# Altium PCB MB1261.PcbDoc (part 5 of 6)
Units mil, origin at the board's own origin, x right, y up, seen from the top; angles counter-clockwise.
Board outline 5119.1 x 2638.79 mil, 6 copper layers (TOP, L2_GND, L3_SIG, L4_VCC, L5_GND, BOTTOM), stack 61 mil thick; 336 components, 316 nets, 1358 pads, 871 vias.
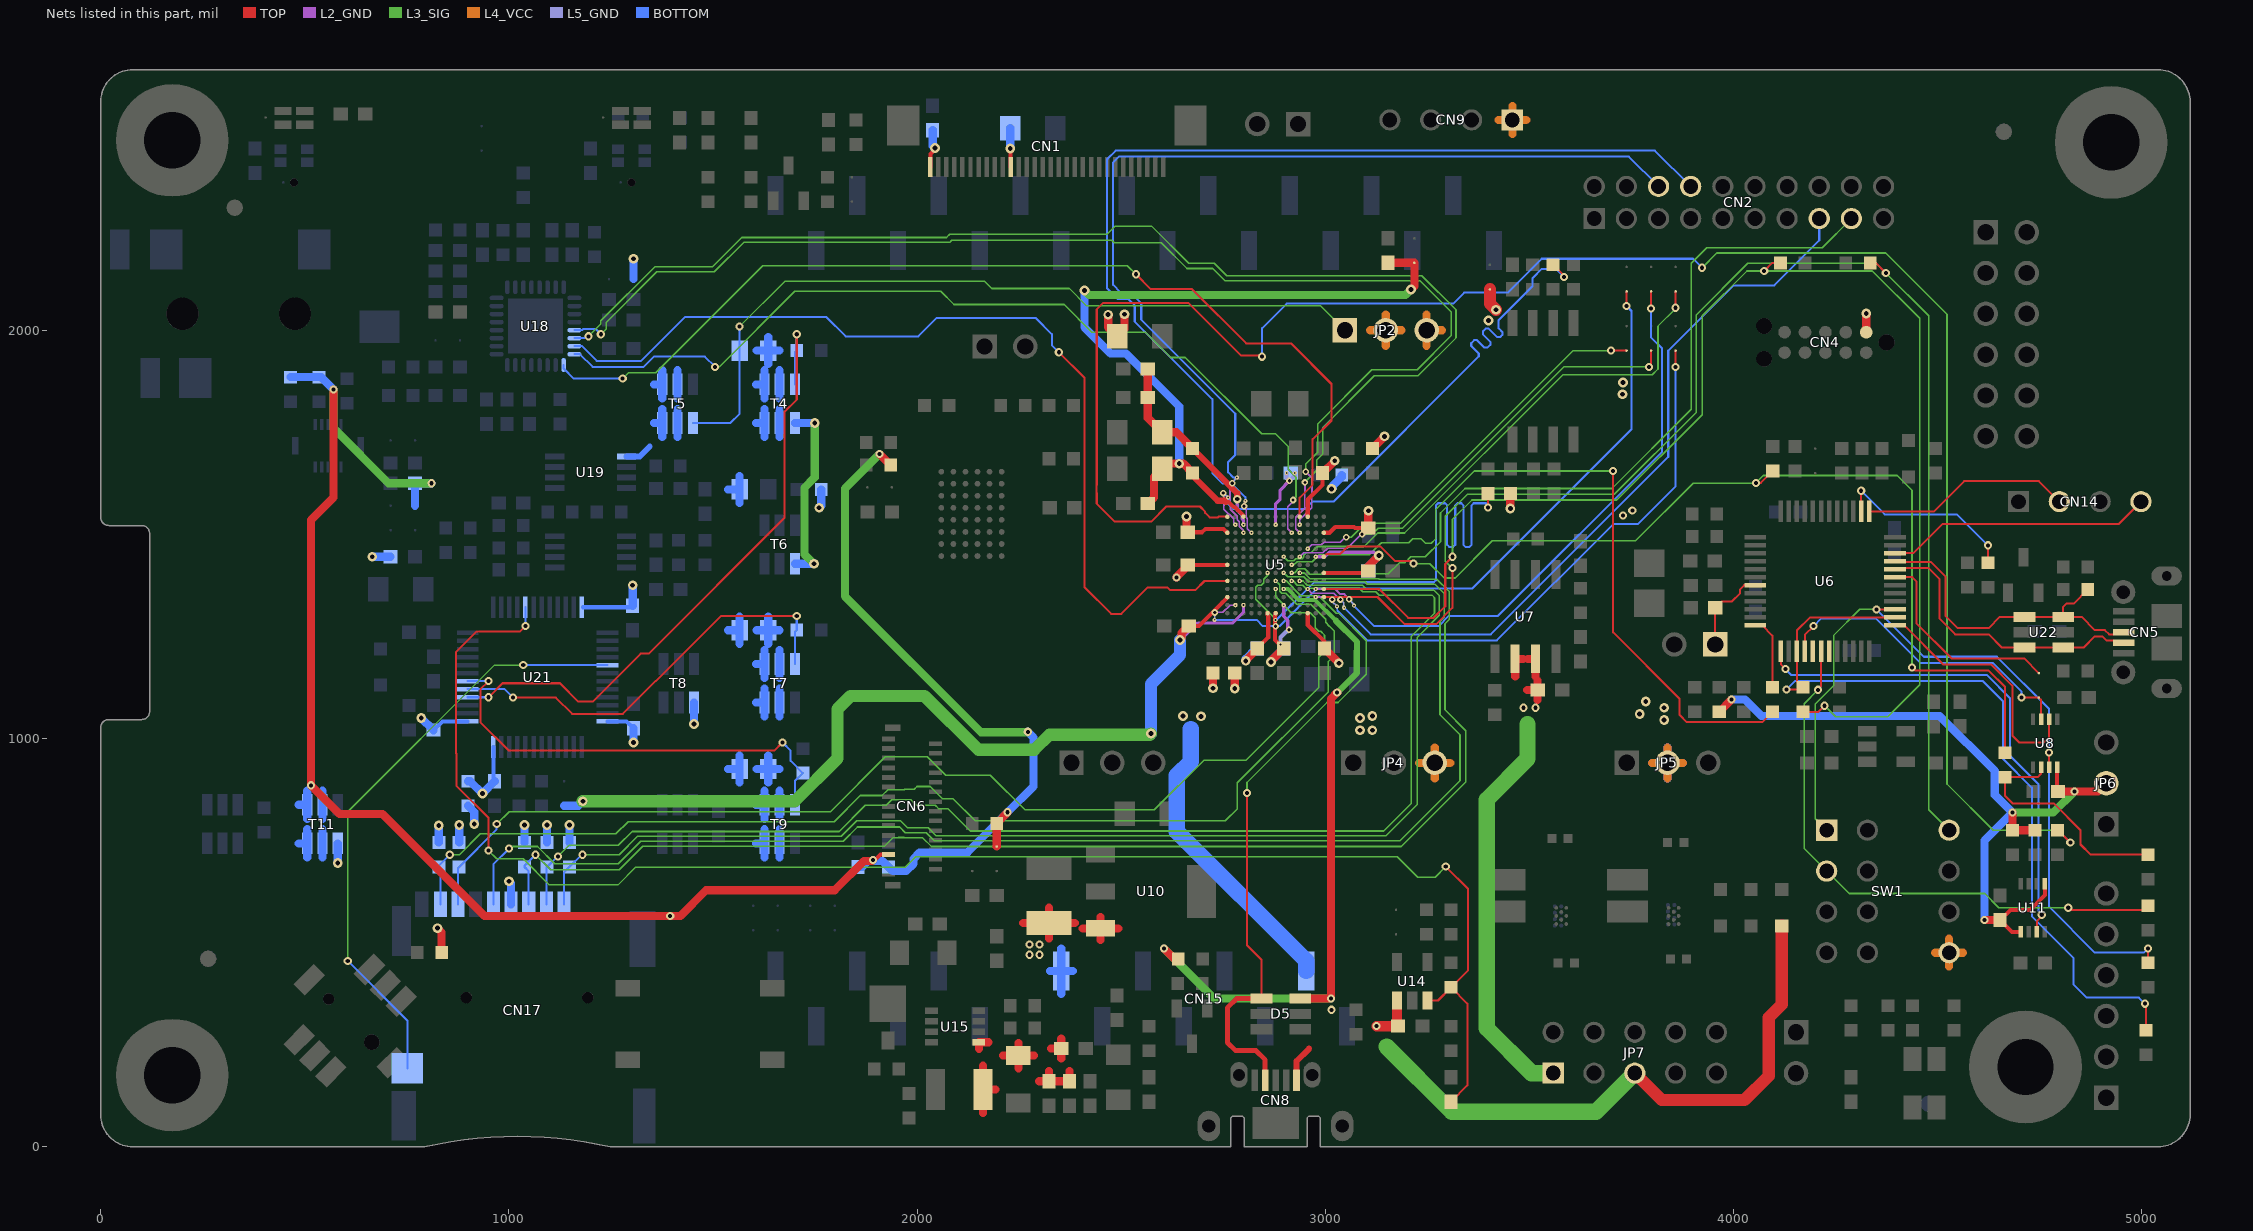
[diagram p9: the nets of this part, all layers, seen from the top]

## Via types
v1: diameter 20, hole 10, TOP to BOTTOM, tented both sides, 317 vias
v2: diameter 24, hole 12, TOP to BOTTOM, tented both sides, 289 vias
v3: diameter 10, hole 4, TOP to L2_GND, tented both sides, 76 vias
v4: diameter 10, hole 4, TOP to L3_SIG, tented both sides, 63 vias
v5: diameter 16, hole 8, L2_GND to L5_GND, tented both sides, 52 vias
v6: diameter 16, hole 8, TOP to BOTTOM, tented both sides, 43 vias
v7: diameter 10, hole 4, L5_GND to BOTTOM, tented both sides, 31 vias

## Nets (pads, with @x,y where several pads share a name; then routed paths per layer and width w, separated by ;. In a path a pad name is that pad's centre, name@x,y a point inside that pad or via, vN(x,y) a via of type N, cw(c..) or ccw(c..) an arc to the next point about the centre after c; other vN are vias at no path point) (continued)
QSPI_BK1_NCS: R26.1 U5.H8 | length 1374.3
  TOP w5: v1(3398.1,1566) R26.1@3398.1,1600
  L3_SIG w3.5: v4(2858.41,1405.31) 2858.41,1399.42 2848.48,1389.49 2848.48,1381.4 2842.77,1375.69 2834.69,1375.69 2828.98,1369.98 2828.98,1361.9 2829,1341.01 2877.95,1292.06 v5(2877.95,1275)
  L5_GND w3.5: v5(2877.95,1275) v7(2877.95,1290)
  BOTTOM w5: v7(2877.95,1290) 2880,1290 2972.49,1382.49 3266,1382.49 3271,1387.49 3271,1571 3276,1576 3293.18,1576 3298.18,1571 3298.18,1474 3303.18,1469 3313.18,1469 3318.18,1474 3318.18,1571 3323.18,1576 3333.18,1576 3338.18,1571 3338.18,1474 3343.18,1469 3353.18,1469 3358.18,1474 3358.18,1571 3363.18,1576 3393.1,1576 3398.1,1571 v1(3398.1,1566)
QSPI_CLK: R7.1 U5.M2 | length 1411.5
  TOP w5: R7.1@3558.1,2160 3585,2133.1 v1(3585,2130)
  L2_GND w3.5: 2751.67,1570 2751.67,1561.33 2775,1538 2775,1528.1 v3(2779.67,1523.43)
  L2_GND w5: v5(2750,1600.87) 2751.67,1599.2 2751.67,1570
  L5_GND w5: v5(2750,1600.87) 2751.1,1600.87 v7(2761.83,1590.14)
  BOTTOM w5: v7(2761.83,1590.14) 2761.83,1574.17 2774,1562 2950,1562 2968,1580 3020,1580 3375.8,1935.8 3375.8,1942.88 3357.38,1961.3 3357.38,1968.38 3364.45,1975.45 3371.53,1975.45 3389.95,1957.03 3397.03,1957.03 3404.1,1964.1 3404.1,1971.18 3385.68,1989.6 3385.68,1996.68 3392.75,2003.75 3399.83,2003.75 3420.75,1982.83 3427.83,1982.83 3433.46,1988.46 3433.46,1995.54 3424.5,2004.5 3424.5,2025 3507.5,2108 3507.5,2127.5 3530,2150 3565,2150 v1(3585,2130)
SAI1_FSA: U5.D1 U18.1 | length 2492
  TOP w5: v1(2536,2137) 2572.5,2100.5 2673.22,2100.5 2806.22,1967.5 2915.75,1967.5 3015,1868.25 3015,1778.78 2969,1732.78 2969,1621.75 2937.16,1589.91 U5.D1@2937.16,1543.11
  L3_SIG w4: v1(1278.64,1881.36) 1292.89,1895.61 1359.39,1895.61 1621.78,2158 2515,2158 v1(2536,2137)
  BOTTOM w5: U18.1@1133.9,1914.72 1133.9,1906.1 1158.64,1881.36 v1(1278.64,1881.36)
SAI1_MCKA: U5.D3 U18.30 | length 3138.6
  L2_GND w3.5: v3(2937.16,1503.74) 2927.41,1513.49 2927.41,1541.41 2950,1564 2950,1606.9
  L2_GND w5: 2950,1606.9 v5(2950,1627)
  L3_SIG w4: v1(1195,1985) 1225,2015 1225,2023.02 1356.98,2155 1498.02,2155 1570.02,2227 2072,2227 2080,2235 2465,2235 2485,2255 2573.98,2255 2664.98,2164 2728.02,2164 2758.52,2133.5 3236.5,2133.5 3320,2050 3320,1981 3227,1888 3120,1888 2994,1762 2994,1697 2979,1682 2979,1656.82 2953,1630.82 2953,1630 v5(2950,1627)
  BOTTOM w5: U18.30@1160.28,1980.47 1184.53,1980.47 1189.06,1985 v1(1195,1985)
SAI1_SCKA: U5.N9 U18.31 | length 2353
  TOP w5: v1(2347,1946) 2410,1883 2410,1633.25 2409.5,1632.75 2409.5,1589.25 2410,1588.75 2410,1370 2475,1305 2500,1305 2565,1370 2613,1370 2619.75,1363.25 2681.58,1363.25 2703.96,1385.63 U5.N9@2759.99,1385.63
  BOTTOM w5: U18.31@1160.28,1960.79 1179.21,1960.79 1215,1925 1323.78,1925 1430.78,2032 1778,2032 1825,1985 2003,1985 2048,2030 2290,2030 2330,1990 2330,1963 v1(2347,1946)
SAI1_SDA: U5.E3 U18.32 | length 2247.9
  L2_GND w3.5: v3(2917.47,1503.74) 2907.72,1513.49 2907.72,1568.03 2921,1581.31 v5(2921,1584)
  L3_SIG w4: v1(1505,1910) 1515,1910 1700,2095 2058.02,2095 2090.02,2063 2360.04,2063 2428.04,1995 2559.16,1995 2621.16,1933 2656.96,1933 2843.96,1746 2878,1746 2909,1715 2909,1659 2928,1640 2928,1591 v5(2921,1584)
  BOTTOM w5: U18.32@1160.28,1941.1 1173.9,1941.1 1205,1910 1330,1910 1355,1935 1480,1935 v1(1505,1910)
SAI1_SDB: U5.D2 U18.29 | length 3084
  L2_GND w3.5: v3(2937.16,1523.43) 2937.16,1535 2967,1564.84 2967,1595.4
  L2_GND w5: v5(2952,1653) 2967,1638 2967,1595.4
  L3_SIG w4: v1(1225,1990) 1238,2003 1238,2019.04 1361.96,2143 1503,2143 1575,2215 2080,2215 2085,2220 2477,2220 2483,2214 2598,2214 2661,2151 2724,2151 2753.5,2121.5 3231.52,2121.5 3308,2045.02 3308,1985.98 3225.02,1903 3114,1903 2981,1770 2981,1700.98 2952,1671.98 v5(2952,1653)
  BOTTOM w5: U18.29@1160.28,2000.16 1180,2000.16 1182.68,2002.84 1212.16,2002.84 v1(1225,1990)
SH0: R84.2 T4.3 U21.4 | length 1582.5
  TOP w5: v1(950,1100.79) 984.21,1135 1125,1135 1170,1090 1205.01,1090 1322.68,1207.67 1342.67,1207.67 1675,1540 1675,1800 1705,1830 v1(1705,1990)
  BOTTOM w5: U21.4@898.74,1100.79 v1(950,1100.79) ; T4.3@1700.5,1867.24 1700.5,1945.5 R84.2@1705,1950 v1(1705,1990)
SH0_D: R85.2 T4.1 T4.2 T4.5 T4.6 | length 439.3
  BOTTOM w20: 1605.18,1772.76 T4.6@1625.7,1772.76 ; 1605.18,1867.24 T4.1@1625.7,1867.24 ; 1606.98,1950 R85.2@1635,1950 ; 1625.7,1738.24 T4.6@1625.7,1772.76 ; 1625.7,1807.28 T4.6@1625.7,1772.76 ; 1625.7,1832.72 T4.1@1625.7,1867.24 ; 1625.7,1901.76 T4.1@1625.7,1867.24 ; 1635,1916.98 R85.2@1635,1950 ; 1635,1983.02 R85.2@1635,1950 ; 1663.02,1950 R85.2@1635,1950 ; 1663.1,1738.24 T4.5@1663.1,1772.76 1663.1,1807.28 ; 1663.1,1832.72 T4.2@1663.1,1867.24 1663.1,1901.76
SH1: R106.2 T7.3 U21.5 | length 1050.3
  TOP w5: v1(1010,1100) 1115,1100 1155,1060 1278.78,1060 1358.78,1140 1360,1140 1520,1300 v1(1705,1300)
  BOTTOM w5: U21.5@898.74,1120.47 989.53,1120.47 v1(1010,1100) ; T7.3@1700.5,1182.24 1700.5,1260.5 R106.2@1705,1265 v1(1705,1300)
SH1_D: R107.2 T7.1 T7.2 T7.5 T7.6 | length 439.3
  BOTTOM w20: 1605.18,1087.76 T7.6@1625.7,1087.76 ; 1605.18,1182.24 T7.1@1625.7,1182.24 ; 1606.98,1265 R107.2@1635,1265 ; 1625.7,1053.24 T7.6@1625.7,1087.76 ; 1625.7,1122.28 T7.6@1625.7,1087.76 ; 1625.7,1147.72 T7.1@1625.7,1182.24 ; 1625.7,1216.76 T7.1@1625.7,1182.24 ; 1635,1231.98 R107.2@1635,1265 ; 1635,1298.02 R107.2@1635,1265 ; 1663.02,1265 R107.2@1635,1265 ; 1663.1,1053.24 T7.5@1663.1,1087.76 1663.1,1122.28 ; 1663.1,1147.72 T7.2@1663.1,1182.24 1663.1,1216.76
SH2: R110.2 T9.3 U21.6 | length 1118.5
  TOP w5: v1(950,1140.16) 930,1120.16 930,1040 1000,970 1650,970 v1(1670,990)
  BOTTOM w5: U21.6@898.74,1140.16 v1(950,1140.16) ; v1(1670,990) 1690,970 1690,945 R110.2@1720,915 1700.5,895.5 T9.3@1700.5,837.24
SH2_D: R111.2 T9.1 T9.2 T9.5 T9.6 | length 439.3
  BOTTOM w20: 1605.18,742.76 T9.6@1625.7,742.76 ; 1605.18,837.24 T9.1@1625.7,837.24 ; 1606.98,925 R111.2@1635,925 ; 1625.7,708.24 T9.6@1625.7,742.76 ; 1625.7,777.28 T9.6@1625.7,742.76 ; 1625.7,802.72 T9.1@1625.7,837.24 ; 1625.7,871.76 T9.1@1625.7,837.24 ; 1635,891.98 R111.2@1635,925 ; 1635,958.02 R111.2@1635,925 ; 1663.02,925 R111.2@1635,925 ; 1663.1,708.24 T9.5@1663.1,742.76 1663.1,777.28 ; 1663.1,802.72 T9.2@1663.1,837.24 1663.1,871.76
SPI2_CLK: SB9.1 U5.B11 | length 1422.9
  TOP w5: v1(3858.1,1910) SB9.1@3858.1,1950
  L2_GND w4: v3(2976.53,1346.26) 3007.74,1346.26 3014,1340 v5(3017,1340)
  L5_GND w3.5: v5(3017,1340) 3017,1334.88 v7(3028.63,1323.25)
  BOTTOM w3.5: v7(3028.63,1323.25) 3028.63,1313.37 3030,1312
  BOTTOM w5: 3030,1312 3102,1240 3420,1240 3705,1525 3765,1525 3858.1,1618.1 v1(3858.1,1910)
SPI2_MISO: SB5.1 U5.B10 | length 1469.8
  TOP w5: v1(3798.1,2053.1) SB5.1@3798.1,2095
  L2_GND w4: v3(2976.69,1366) 3022,1366
  L2_GND w5: 3022,1366 3024,1366 3036.5,1353.5 3046.5,1353.5 3058,1342 v5(3058,1341)
  L5_GND w3.5: v5(3058,1341) 3070,1329 v7(3070,1325.2)
  BOTTOM w5: v7(3070,1325.2) 3120.2,1275 3277.75,1275 3302.75,1300 3423,1300 3825,1702 3825,1955 3798.1,1981.9 v1(3798.1,2053.1)
SPI2_MISOS: CN2.9 U5.E8 | length 1992.1
  L3_SIG w3.5: v4(2917.47,1405.31) 2924.43,1405.31 2934.18,1415.06 2949.33,1415.06 2962.14,1402.25 3087.38,1402.25 3088.13,1403 3132,1403
  L3_SIG w4: 3132,1403 3153.94,1403 3181.94,1431 3195.15,1431 3209.15,1445 3245,1445 3282,1482 3282,1552 3342,1612 3702,1612 3896,1806 3896,2164 3934,2202 4217.27,2202 CN2.9@4288.69,2273.42
SPI2_MOSI: SB4.1 U5.M12 | length 1646.4
  TOP w5: v1(3738.1,2058.9) SB4.1@3738.1,2095
  L2_GND w3.5: v5@2730,1308.4 2748.4,1308.4 2766.57,1326.57 v3(2779.67,1326.57)
  L2_GND w5: v5(2728.9,1308.4) v5@2730,1308.4
  L5_GND w3.5: v7(2728.9,1290.4) v5(2728.9,1308.4)
  BOTTOM w5: v7(2728.9,1290.4) 2831.6,1290.4 2847,1275 2887.73,1275 2980.22,1367.49 3360.49,1367.49 3750,1757 3750,2047 v1(3738.1,2058.9)
SPI2_MOSIS: CN2.8 U5.C10 | length 1911.1
  L2_GND w3.5: v3(2956.84,1365.94) 2957.06,1365.94 2966.94,1356.06 3020.94,1356.06 v5(3037,1340)
  L5_GND w3.5: v5(3037,1340) 3045,1332 3045,1325.2
  L5_GND w5: 3045,1325.2 3045,1321.1 v7(3046.06,1320.04)
  BOTTOM w5: v7(3046.06,1320.04) 3111.1,1255 3405.37,1255 3840,1689.63 3840,1950 4000,2110 4100,2110 4209.95,2219.95 CN2.8@4209.95,2273.42
STL_USB_DM: CN5.2 U6.32 U22.1 U22.6 | length 716.4
  TOP w4.8: U6.32@4395.36,1414.53 4418.66,1414.53 4421,1416.87 4477.91,1416.87 4504,1390.78 4504,1293.78 4542.78,1255 4625,1255 4657.4,1222.6 U22.6@4712.76,1222.6 U22.1@4807.24,1222.6 4857.6,1222.6 4885,1250 4903.48,1250 4913.78,1239.7 4929.71,1239.7 4935,1234.41 CN5.2@4955.7,1234.41
STL_USB_DP: CN5.3 R37.2 U6.33 U22.3 U22.4 | length 819.8
  TOP w4.8: U6.33@4395.36,1434.21 4418.66,1434.21 4421,1431.87 4484.13,1431.87 4519,1397 4519,1300 4549,1270 4625,1270 4652.4,1297.4 U22.4@4712.76,1297.4 U22.3@4807.24,1297.4 ; R37.2@4868.1,1365 4833.1,1330 4815,1330 4807.24,1322.24 U22.3@4807.24,1297.4 ; CN5.3@4955.7,1260 4935.3,1260 4930,1254.7 4920,1254.7 4909.7,1265 4885,1265 4852.6,1297.4 U22.3@4807.24,1297.4
STLINK_RX: U6.13 U11.7 | length 1238.1
  TOP w5: U6.13@4115.83,1213.74 4115.83,1181.17 v1(4127,1170) ; U11.7@4742.94,525.94 4742.94,551.94 4755,564 v1(4755,568)
  BOTTOM w5: v1(4127,1170) 4142,1155 4621,1155 4677,1099 4677,958 4747,888 4747,578 4755,570 v1(4755,568)
STLINK_TX: R46.1 U6.12 | length 179.2
  TOP w5: U6.12@4052.84,1276.73 4070,1276.73 4095,1251.73 R46.1@4095,1125
STM_JTCK: CN14.2 U6.37 | length 517
  TOP w5: U6.37@4332.37,1556.26 4491.26,1556.26 4565,1630 4748.1,1630 CN14.2@4798.1,1580
STM_JTMS: CN14.4 U6.34 | length 655
  TOP w5: U6.34@4395.36,1453.9 4440.45,1453.9 4511.55,1525 4943.1,1525 CN14.4@4998.1,1580
STM_RST: C24.1 JP10.1 U6.7 | length 216
  TOP w5: JP10.1@3955,1230 C24.1@3955,1320 3970,1335 3995.05,1335 4016,1355.95 4016,1365 4026.16,1375.16 U6.7@4052.84,1375.16
STMOD+_ADC: CN2.13 U5.L3 | length 2458.8
  L2_GND w3.5: 2766.67,1570 2766.67,1561.33 2784.16,1543.84 2784.16,1535.84 2789.61,1530.39 2789.61,1519.39 2799.36,1509.64 v3(2799.36,1503.75)
  L2_GND w5: 2766.67,1570 2766.67,1618.45 2771.5,1623.28 2771.5,1624.5 v5(2772,1625)
  L5_GND w5: v5(2772,1625) 2772,1627.81 v7(2783.25,1639.06)
  BOTTOM w5: v7(2783.25,1639.06) 2774.72,1639.06 2762,1651.78 2762,1677 2779.26,1694.26 2779.26,1795.74 2549,2026 2549,2066 2522,2093 2498,2093 2480,2111 2480,2411 2494,2425 3743.41,2425 CN2.13@3816.25,2352.16
STMOD+_PWM: CN2.14 U5.K3 | length 2567.5
  L2_GND w3.5: v5(2800.79,1568.34) 2806,1563.13 2806,1541.58 2809.11,1538.47 2809.11,1513.67 v3(2819.04,1503.74)
  L5_GND w3.5: v5(2800.79,1568.34) 2800.79,1578.79 v7(2804,1582)
  BOTTOM w5: v7(2804,1582) 2804,1591 2770.94,1624.06 2749,1624.06 2723,1650.06 2723,1830.78 2533,2020.78 2533,2060.78 2517.78,2076 2492,2076 2465,2103 2465,2418.78 2486.22,2440 3807.15,2440 CN2.14@3894.99,2352.16
SWCLK: R4.2 R47.1 U5.A10 | length 3427.3
  TOP w5: U5.A10@2996.21,1365.94 3132.06,1365.94 3203,1295 3265,1295 3293.7,1323.7 3293.7,1427.26 v1(3311.47,1445.03) ; v1(4075,2145) 4095,2165 R4.2@4115,2165 ; R47.1@4170,1065 4208.1,1065 v1(4223.1,1080)
  L3_SIG w4: v1(3311.47,1445.03) 3311.47,1536.47 3359,1584 3714,1584 3923,1793 3923,2035.02 4032.98,2145 v1(4075,2145) 4340,2145 4456,2029 4456,1131 4378,1053 4250.1,1053 v1(4223.1,1080)
SWDIO: R5.2 SW1.8 U5.A11 | length 3553.5
  TOP w5: U5.A11@2996.21,1346.26 3127.74,1346.26 3194,1280 3271.22,1280 3311.2,1319.98 v1(3311.2,1417) ; R5.2@4335,2165 4348,2165 v1(4373,2140)
  L3_SIG w4: v1(3311.2,1417) 3294,1434.2 3294,1544 3348,1598 3708,1598 3909,1799 3909,2038 4035,2164 4349,2164 v1(4373,2140) 4478,2035 4478,825.1 SW1.8@4528.1,775
SWO: R16.2 R51.1 U5.A6 | length 2498.4
  TOP w5: U5.A6@2996.21,1444.69 3003.52,1452 3037,1452 3055.5,1470.5 3134.75,1470.5 3171.25,1434 3210.2,1434 v1(3216.2,1428) ; v1(4055,1626) 4067,1626 R16.2@4096,1655 ; v1(4437,1174) 4445,1166 4625,1166 4665,1126 R51.1@4665,965
  L3_SIG w4: v1(3216.2,1428) 3256,1428 3291,1393 3318,1393 3409,1484 3760,1484 3901,1625 4054,1625 v1(4055,1626) 4073,1644 4401,1644 4437,1608 v1(4437,1174)
SWO_MCU: R51.2 R56.2 U8.6 | length 583.5
  TOP w5: U8.6@4753.26,928.94 4753.26,913.26 4745,905 R51.2@4665,905 4665,859 4683.4,840.6 4784.4,840.6 4850,775 4850,740 4875,715 R56.2@5015,715
T50_4: JP2.1 R85.1 T5.4 | length 1916.5
  L3_SIG w4: v1(1565,2009) 1676,2120 2165,2120 2183,2102 2373,2102 2415,2060 2988.1,2060 JP2.1@3048.1,2000
  BOTTOM w5: T5.4@1450.5,1772.76 1542.76,1772.76 1565,1795 R85.1@1565,1950 v1(1565,2009)
T50_6: R95.1 R107.1 R111.1 T5.1 T5.2 T5.5 T5.6 U19.5 | length 666.6
  BOTTOM w14: U19.5@1287.99,1690.29 1320.29,1690.29 1345,1715
  BOTTOM w20: 1355.18,1772.76 T5.6@1375.7,1772.76 ; 1355.18,1867.24 T5.1@1375.7,1867.24 ; 1375.7,1738.24 T5.6@1375.7,1772.76 ; 1375.7,1807.28 T5.6@1375.7,1772.76 ; 1375.7,1832.72 T5.1@1375.7,1867.24 ; 1375.7,1901.76 T5.1@1375.7,1867.24 ; 1413.1,1738.24 T5.5@1413.1,1772.76 1413.1,1807.28 ; 1413.1,1832.72 T5.2@1413.1,1867.24 1413.1,1901.76 ; 1536.98,925 R111.1@1565,925 ; 1536.98,1265 R107.1@1565,1265 ; 1536.98,1610 R95.1@1565,1610 ; 1565,891.98 R111.1@1565,925 ; 1565,958.02 R111.1@1565,925 ; 1565,1231.98 R107.1@1565,1265 ; 1565,1298.02 R107.1@1565,1265 ; 1565,1576.98 R95.1@1565,1610 ; 1565,1643.02 R95.1@1565,1610
T_JRST: U6.19
T_JTCK: R47.2 R66.2 U6.15 U6.26 | length 2025.4
  TOP w5: v1(4130,1120) 4165,1120 R47.2@4170,1125 4155.2,1139.8 U6.15@4155.2,1213.74 4155.2,1264.2 4187.42,1296.42 U6.26@4395.36,1296.42 ; v1(5008,350) 5010,348 R66.2@5010,285
  BOTTOM w5: v1(4130,1120) 4150,1140 4611,1140 4660,1091 4660,950 4731,879 4731,564 4832.5,462.5 4832.5,397.5 4865,365 4993,365 v1(5008,350)
T_JTDI: U6.17
T_JTDO: SB13.2 U6.16 U8.3 | length 774.2
  TOP w5: U6.16@4174.89,1213.74 4174.89,1253.89 v1(4196,1275) ; v1(4705,1100) SB13.2@4748.1,1100 4753.26,1094.84 U8.3@4753.26,1047.06
  BOTTOM w5: v1(4196,1275) 4215,1294 4348,1294 4457,1185 4635,1185 4705,1115 v1(4705,1100)
T_JTMS: R63.2 SW1.1 U6.27 U8.7 | length 2057
  TOP w5: v1(4350,1316.1) U6.27@4395.36,1316.1 ; U8.7@4772.94,928.94 v1(4772.94,965) ; R63.2@5015,450 v1(5015,485)
  L3_SIG w4: SW1.1@4228.1,775 4200,803.1 4200,1084 4245,1129 4245,1252.2 4308.9,1316.1 v1(4350,1316.1)
  BOTTOM w5: v1(4350,1316.1) 4466.1,1200 4645,1200 4772.94,1072.06 v1(4772.94,965) 4772.94,587.06 4885,475 5005,475 v1(5015,485)
T_NRST: R59.2 SW1.2 U6.18 | length 1409
  TOP w5: v1(4207,1119) 4207,1121 4214.26,1128.26 U6.18@4214.26,1213.74 ; v1(4820,585) 4825,580 5005,580 R59.2@5015,590
  L3_SIG w4: v1(4207,1119) 4173,1085 4173,730.1 SW1.2@4228.1,675 4283.1,620 4615,620 4650,585 v1(4820,585)
T_SWDIO_IN: U6.25 U8.2 | length 617.4
  TOP w5: U6.25@4395.36,1276.73 4418.27,1276.73 4514,1181 4631.22,1181 4683,1129.22 4683,1007 4700,990 4760,990 4772.94,1002.94 U8.2@4772.94,1047.06
T_SWO: SB13.1 U6.31 | length 510.2
  TOP w5: U6.31@4395.36,1394.84 4437.97,1394.84 4448,1384.81 4448,1282 4534,1196 4712.1,1196 SB13.1@4748.1,1160
U5V_ST_LINK: C29.2 JP7.1 U7.6 U7.7 | length 1192.7
  TOP w20: 3465,1151.78 U7.6@3465,1194.8 3484.02,1194.8 ; 3494.48,1118.1 C29.2@3520,1118.1 ; 3495.98,1194.8 U7.7@3515,1194.8 3515,1151.78 ; 3520,1094.08 C29.2@3520,1118.1 ; 3520,1142.12 C29.2@3520,1118.1
  L3_SIG w40: 3495,1035 3495,950 3395,850 3395,290 3505,180 JP7.1@3558.1,180
  other v1: 3485,1075 3515,1075
UART1_RTS: SB6.1 U5.F6 | length 1326.4
  TOP w5: v1(3858.1,2055) SB6.1@3858.1,2095
  L3_SIG w3.5: v4(2897.79,1444.69) 2907.54,1434.94 2922.23,1434.94 2927.79,1440.5 2943.25,1440.5 2947.09,1444.34 2947.09,1448.73 2952.8,1454.44 2964.44,1454.44 2966.25,1456.25
  L3_SIG w4: 2966.25,1456.25 2980,1470 3095.02,1470 3128.02,1503 3193.96,1503 3581.96,1891 3801,1891 3815,1905 3815,2010 3858.1,2053.1 v1(3858.1,2055)
UART1_RX: SB8.1 U5.D6 | length 1090.4
  TOP w5: v1(3792.5,1910) 3798.1,1915.6 SB8.1@3798.1,1950
  L2_GND w3.5: v3(2937.16,1444.69) 2946.91,1454.44 2994.05,1454.44 3005.36,1465.75 3053.36,1465.75 3087.61,1500 v5(3090,1500)
  L3_SIG w3.5: v5(3090,1500) 3114.05,1500 3129.05,1515 3129.7,1515
  L3_SIG w4: 3129.7,1515 3188.98,1515 3583.98,1910 v1(3792.5,1910)
UART1_TX: SB7.1 U5.C5 | length 982.4
  TOP w5: v1(3700,1950) SB7.1@3738.1,1950
  L2_GND w3.5: v3(2956.84,1464.37) 2966.77,1474.3 2990.3,1474.3 2997,1481 3037,1481 3048.79,1492.79 v5(3051.16,1492.79)
  L3_SIG w3.5: v5(3051.16,1492.79) 3051.37,1493 3063,1493 3085,1515 3111.7,1515 3120.7,1524
  L3_SIG w4: 3120.7,1524 3123.7,1527 3184,1527 3607,1950 v1(3700,1950)
USART2_RX: R46.2 U5.E7 | length 1843.7
  TOP w5: v1(3705,1655) 3705,1260 3867.5,1097.5 3867.5,1057.5 3885,1040 4070,1040 R46.2@4095,1065
  L3_SIG w3.5: v4(2917.47,1425) 2922.9,1425 2930.9,1433 2968,1433 2985,1450 3107.89,1450 3132,1474.11
  L3_SIG w4: 3132,1474.11 3135.88,1477.99 3136.97,1477.99 3137.98,1479 3203.98,1479 3213.98,1489 3234.45,1489 3245.45,1478 3259.55,1478 3270,1488.45 3270,1560 3365,1655 v1(3705,1655)
USART2_TX: R55.1 U5.N1 | length 4770.6
  TOP w5: U5.N1@2759.99,1543.11 2738.87,1543.11 2737.26,1541.5 2716.75,1541.5 2705.49,1552.76 2705.49,1555.51 2693,1568 2610,1568 2573,1531 2484,1531 2440,1575 2440,1601.18 2439.5,1601.68 2439.5,1620.32 2440,1620.82 2440,2051 2456,2067 2664.28,2067 2793.78,1937.5 2842.5,1937.5 v1(2845,1935) ; R55.1@4793.1,775 4795,775 v1(4825,745)
  L3_SIG w4: v1(3923,2153) 3959,2189 4373,2189 4523,2039 4523,888 4636,775 4795,775 v1(4825,745)
  BOTTOM w5: v1(2845,1935) 2845,2005 2905,2065 3313,2065 3340,2092 3447,2092 3530,2175 3901,2175 v1(3923,2153)
USB_OTGFS_ID: CN8.4 D5.1 U5.F9 | length 1629
  TOP w5: v1(2808,866) 2808,493 2843.65,457.35 D5.1@2843.65,362.4
  TOP w12: D5.1@2843.65,362.4 2782.4,362.4 2760,340 2760,255 2780,235 2830,235 2852.51,212.49 CN8.4@2852.51,162.8
  L3_SIG w3.5: v4(2897.79,1385.63) 2903.58,1385.63 2939.21,1350 2984,1350 3027.03,1306.97 3030,1306.97
  L3_SIG w4: v1(2808,866) 2808,892 3004,1088 3031,1088 3100,1157 3100,1239.37 3032.4,1306.97 3030,1306.97
USB_OTGFS_OVRCR: LD7.2 R64.2 U14.3 U21.17 | length 3922.4
  TOP w5: v1(950,725) 950,805 871,884 871,962.78 870,963.78 870,1211 921,1262 1027.47,1262 v1(1040.47,1275) ; U14.3@3250.5,357.76 3275.86,357.76 R64.2@3308.1,390 ; v1(3295,686) 3350,631 3350,431.9 R64.2@3308.1,390 ; LD7.2@3308.1,110 3348,149.9 3348,350.1 R64.2@3308.1,390
  L3_SIG w4: v1(950,725) 970,705 1035,705 1099,641 1266.94,641 1309.94,684 1970.88,684 1996.88,710 3176,710 3226,660 3269,660 v1(3295,686)
  BOTTOM w5: v1(1040.47,1275) U21.17@1040.47,1321.26
USB_OTGFS_VBUS: C54.1 CN8.1 D4.1 D5.6 JP7.5 R62.1 U5.F10 U14.1 | length 3394.7
  TOP w15: CN8.1@2929.28,162.8 2929.28,209.28 2960,240
  TOP w20: v1(2605,485) 2630,460 R62.1@2640,460 ; D5.6@2938.13,362.4 v1(3014,362.4) 3014,1097 v1(3029,1112)
  TOP w25: v1(3125,295) C54.1@3178.1,295 3175.7,297.4 U14.1@3175.7,357.76
  TOP w30: JP7.5@3758.1,180 3824.1,114 4027,114 4086,173 4086,316 4118.1,348.1 D4.1@4118.1,540.71
  L3_SIG w10: v4@2899,1365.94 2908.06,1365.94 2934.75,1339.25 2974.75,1339.25 3025.85,1288.15
  L3_SIG w15: 3025.85,1288.15 3077.5,1236.5 3077.5,1214.85 3077,1214.35 3077,1160 v1(3029,1112)
  L3_SIG w20: v1(2605,485) 2727.6,362.4 v1(3014,362.4)
  L3_SIG w40: 3150,245 3310,85 3663.1,85 JP7.5@3758.1,180
  other v1: 3015,335
  other v4: 2897.79,1365.94
USB_RENUMN: R35.2 U6.38 | length 459.2
  TOP w5: U6.38@4312.68,1556.26 v1(4312.68,1606.68) ; R35.2@4623.1,1430 v1(4623.1,1473)
  BOTTOM w5: v1(4312.68,1606.68) 4370.36,1549 4547.1,1549 v1(4623.1,1473)
USD_CLK: CN17.5 U5.F8 | length 3511.9
  L3_SIG w3.5: v4(2897.79,1405.31) 2907.54,1395.56 2929.82,1395.56 2930,1395.38 2947.06,1395.38 2958.94,1383.5 3097.52,1383.5 3103,1378.02 3132,1378.02
  L3_SIG w4: v1(1000,730) 1005,735 1070,735 1112,693 1268,693 1323,748 1818.94,748 1853.94,783 1957.02,783 1971.12,768.9 2022.14,768.9 2042.04,749 3182.96,749 3330,896.04 3330,1009 3281,1058 3281,1286.03 3291.25,1296.28 3291.25,1354.82 3268.07,1378 3132.02,1378
  BOTTOM w5: CN17.5@961.8,593.35 961.8,691.8 v1(1000,730)
USD_CMD: CN17.3 R120.1 U5.D8 | length 3416.1
  TOP w3.5: U5.D8@2937.16,1405.31 U5.D8@2937.16,1405.31 2937.57,1404.98 2937.9,1405.31 2937.9,1405.14 v4(2938.07,1405.14)
  L3_SIG w4: v1(1065,715) 1102,678 1269.98,678 1327.98,736 1920,736 1940.9,756.9 1954.11,756.9 1954.21,757 1968.31,757 1968.41,756.9 2013.1,756.9 2035,735 3185.94,735 3344,893.06 3344,1019.02 3293,1070.02 3293,1281.05 3303.25,1291.3 3303.25,1359.8 3273.05,1390 3137,1390 ; v4(2938.07,1405.14) 2948.27,1405.14 2962.16,1391.25 3130.75,1391.25 3131.97,1390.03 3136.97,1390.03
  BOTTOM w5: CN17.3@1048.41,593.35 1048.41,674.69 R120.1@1038.1,685 1038.1,688.1 v1(1065,715)
USD_D0: CN17.7 R121.1 U5.G10 | length 2822.7
  L3_SIG w3.5: v4(2878.1,1365.94) 2878.1,1346.9 2917,1308 2963.04,1308 2975,1296.04 2975,1271.07 2984,1262.07
  L3_SIG w4: v1(970,790) 1000.5,820.5 1787.48,820.5 1921.98,955 2025,955 2070,910 2179,910 2264,825 2581,825 2702,946 2805,946 2983.5,1124.5 2983.5,1198.52 2998,1213.02 2998,1253.04 2988.97,1262.07 2984,1262.07
  BOTTOM w5: CN17.7@875.19,593.35 875.19,682.09 R121.1@878.1,685 970,776.9 v1(970,790)
USD_D1: CN17.8 R122.1 U5.G9 | length 2921.8
  L3_SIG w3.5: v4(2878.1,1385.63) 2887.85,1375.88 2887.85,1360.66 2890.18,1358.33 2893.33,1355.19 2902.16,1355.19 2902.35,1355 2902.84,1355 2929.34,1328.5 2963.76,1328.5 3000.53,1291.73 3000.53,1285.53 ; 3000.52,1285.52 3000.52,1284.48 3010,1275
  L3_SIG w4: v1(855,715) 879,715 930,766 1261.94,766 1291.94,796 1796.94,796 1860.94,860 1914,860 1928.38,874.38 1968.17,874.38 1969.23,875.44 1993.15,875.44 1999.71,882 2032,882 2062,852 2088,852 2142,798 2755,798 2784,827 2784,891.02 3007.5,1114.52 3007.5,1188.56 3022,1203.06 3022,1263 3010,1275
  BOTTOM w5: CN17.8@831.88,593.35 831.88,681.22 R122.1@828.1,685 828.1,688.1 v1(855,715)
USD_D2: CN17.1 R118.1 U5.D9 | length 3159.2
  L3_SIG w4: v1(1180,715) 1270,715 1315,760 1813.96,760 1851.96,798 1959,798 1976.1,780.9 2027.12,780.9 2047.02,761 3147.98,761 3225,838.02 3225,1247.01 3279.25,1301.26 3279.25,1349.84 3266.09,1363 3130.97,1363 3127.22,1366.75 3099.25,1366.75 3090.75,1375.25 2955.45,1375.25 2945.07,1385.63 v4(2937.16,1385.63)
  BOTTOM w5: CN17.1@1135.03,593.35 1135.03,671.93 R118.1@1148.1,685 1178.1,715 v1(1180,715)
USD_D3: CN17.2 R119.1 U5.E9 | length 3232.4
  L3_SIG w3.5: v4(2917.47,1385.63) 2921.37,1385.63 2931.31,1375.69 2944.04,1375.69 2952.23,1367.5 3083.11,1367.5 3091.61,1359 3124,1359 3132,1351
  L3_SIG w4: v1(1120,711) 1147,738 1268,738 1302,772 1808.98,772 1872.98,836 1923.96,836 1937.96,850 1984.92,850 1998.92,836 2044.04,836 2052.04,828 2075.02,828 2130.02,773 3143,773 3210,840 3210,1249 3267.25,1306.25 3267.25,1344.86 3261.11,1351 3132,1351
  BOTTOM w5: CN17.2@1091.72,593.35 1091.72,683.62 R119.1@1093.1,685 1119.1,711 v1(1120,711)
USD_DETECT: CN17.10 U21.29 | length 1474
  L3_SIG w4: v1(605,455) 605,820 964.53,1179.53 v1(1035,1179.53)
  BOTTOM w5: v1(605,455) 751.17,308.83 CN17.10@751.17,191.77 ; v1(1035,1179.53) U21.29@1241.26,1179.53
VDD: C60.1 C61.1 CN1.20 CN1.30 CN4.1 CN15.2 CN17.4 JP5.2 R21.1 R27.2 R42.1 R43.1 R60.1 R94.2 R114.1 R118.2 R119.2 R120.2 R121.2 R122.2 SB3.1 SB18.1 SW1.5 T8.4 T11.4 | length 2213.9
  TOP w10: CN1.30@2032.23,2400 2032.23,2431.65 2043.7,2443.12 v2(2043.7,2445.96) ; v2(2228.1,2445.06) 2229.08,2444.08 CN1.20@2229.08,2400
  TOP w20: v2(825,535) 835,525 R60.1@835,475 ; v2(2725,1122.9) R42.1@2725,1160 ; v2(2778.1,1122.1) R43.1@2778.1,1160 ; R21.1@3115,1710 v2(3145,1740) ; v2(3453.1,1562.9) R27.2@3453.1,1600 ; CN4.1@4325,1995 v2(4325,2041)
  TOP w30: SB3.1@3403.1,2100 3403.1,2064.9 v2(3418,2050)
  L4_VCC w20: 3800.08,940 JP5.2@3838.1,940 ; 3838.1,901.98 JP5.2@3838.1,940 ; 3838.1,978.02 JP5.2@3838.1,940 ; 3876.12,940 JP5.2@3838.1,940 ; 4494.08,475 SW1.5@4528.1,475 ; 4528.1,440.98 SW1.5@4528.1,475 ; 4528.1,509.02 SW1.5@4528.1,475 ; 4562.12,475 SW1.5@4528.1,475
  BOTTOM w20: v2(580.5,695) T11.4@580.5,742.76 ; R122.2@828.1,745 v2(828.1,786.9) ; R121.2@878.1,745 v2(878.1,788.1) ; R114.1@900,835 915,820 v2(915,790) ; v2(1000,650) 1005.11,644.89 CN17.4@1005.11,593.35 ; R120.2@1038.1,745 v2(1038.1,788.1) ; R119.2@1093.1,745 v2(1093.1,788.1) ; R118.2@1148.1,745 v2(1148.1,788.1) ; SB18.1@1305,2125 v2(1305,2175) ; v2(1453.6,1035) T8.4@1453.6,1087.76 ; v2(1760,1565) 1765,1570 R94.2@1765,1610 ; C60.1@2038.1,2490 2038.1,2451.56 v2(2043.7,2445.96) ; v2(2228.1,2445.06) C61.1@2228.1,2495 ; 3800.08,940 JP5.2@3838.1,940 ; 3838.1,901.98 JP5.2@3838.1,940 ; 3838.1,978.02 JP5.2@3838.1,940 ; 3876.12,940 JP5.2@3838.1,940
  BOTTOM w40: 2670,1023 2670,943 2636,909 2636,772 2953.1,454.9 CN15.2@2953.1,430
  other v1: 3729,1546 3752,1558
  other v2: 3085,1020 3115,1020 3830,1045 3085,1050 2695,1054 2651,1055 3115,1055 3770,1060 3830,1075 3785,1090 3727.88,1843.01 3729.04,1871.99 3399.95,2023.49
VDD1: C93.1 C101.1 C102.1 C103.1 CN9.1 JP2.3 L8.1 R114.2 T4.4 T6.4 U21.1 U21.24 U21.36 U21.48 | length 1345.6
  L3_SIG w20: v2(1747,1427.76) 1724,1450.76 1724,1614 1749,1639 v2(1749,1772.76)
  L4_VCC w20: 3248.1,1961.98 JP2.3@3248.1,2000 ; 3248.1,2038.02 JP2.3@3248.1,2000 ; 3286.12,2000 JP2.3@3248.1,2000 ; 3424.08,2515 CN9.1@3458.1,2515 ; 3458.1,2480.98 CN9.1@3458.1,2515 ; 3458.1,2549.02 CN9.1@3458.1,2515 ; 3492.12,2515 CN9.1@3458.1,2515
  BOTTOM w10: C102.1@815,1020 836.73,1041.73 U21.1@898.74,1041.73 ; U21.48@961.73,978.74 961.73,898.27 C103.1@965,895 ; U21.24@1181,1321.26 1301.84,1321.26 C93.1@1303.1,1325 ; U21.36@1241.26,1041.73 1288.27,1041.73 C101.1@1305,1025
  BOTTOM w20: v2(665,1445) L8.1@710,1445 ; v2(785,1050) C102.1@815,1020 ; R114.2@900,895 905,895 v2(935,865) C103.1@965,895 ; C93.1@1303.1,1325 v2(1303.1,1375) ; v2(1305,990) C101.1@1305,1025 ; T6.4@1700.5,1427.76 v2(1747,1427.76) ; T4.4@1700.5,1772.76 v2(1749,1772.76)
VDD_LCD: C82.1 C104.1 CN6.25 R52.2 R87.2 R88.1 R117.1 R129.2 SB14.1 SB21.2 T11.1 T11.2 T11.5 T11.6 | length 5309.6
  TOP w10: v1(1892,702) 1894,700 1894.78,700 1910,715.22 CN6.25@1930.26,715.22
  TOP w20: v1(570,1855) 570,1590 515,1535 v1(515,885) 585,815 690,815 940,565 v1(1395,565) 1420,565 1483,628 1798,628 1870,700 1890,700 v1(1892,702) ; v1(1908,1697) R129.2@1935,1670 ; SB14.1@2195,735 R52.2@2195,791.38 2221.62,818 v1(2221.62,819)
  L3_SIG w20: v1(570,1855) 570,1760 705,1625 v1(810,1625) ; v1(1908,1697) 1823,1612 1823,1348 2156,1015 2270,1015 2271.04,1016.04 v1(2271.1,1016.04)
  BOTTOM w20: R88.1@465,1885 R87.2@535,1885 540,1885 v1(570,1855) ; 485.18,742.76 T11.6@505.7,742.76 ; 485.18,837.24 T11.1@505.7,837.24 ; 505.7,708.24 T11.6@505.7,742.76 ; 505.7,777.28 T11.6@505.7,742.76 ; 505.7,802.72 T11.1@505.7,837.24 ; 505.7,871.76 T11.1@505.7,837.24 ; 543.1,708.24 T11.5@543.1,742.76 543.1,777.28 ; 543.1,802.72 T11.2@543.1,837.24 543.1,871.76 ; SB21.2@770,1570 C82.1@770,1625 v1(810,1625) ; C104.1@1855,685 1864.78,685 1879.78,700 1890,700 v1(1892,702) 1894,700 1915,700 R117.1@1930,685 1940,675 1973.19,675 1990.9,692.71 1990.9,704.9 2006,720 2122.62,720 v1(2221.62,819) 2285,882.38 2285,1002.14 v1(2271.1,1016.04)
VDD_MCU: C6.1 C12.1 C17.1 C18.1 C21.1 C22.1 C25.1 C26.1 C27.1 C28.1 C81.1 C89.1 C97.1 C98.1 JP2.2 JP4.3 R93.2 SB24.1 U5.A3 U5.A8 U5.B6 U5.C1 U5.C13 U5.F12 U5.G2 U5.G13 U5.H13 U5.L12 U5.N3 U5.N7 U5.N11 | length 4576
  TOP w10: C21.1@2663.1,1425 U5.N7@2759.99,1425 ; C18.1@2663.1,1505 2698,1505 2706,1513 2750.73,1513 U5.N3@2759.99,1503.74 ; C25.1@2665,1275 2690,1275 2746.49,1331.49 2746.49,1332.17 2759.99,1345.67 U5.N11@2759.99,1346.26 ; C26.1@2833.1,1220 2860,1246.9 2860,1300.3 2858.41,1301.89 U5.H13@2858.41,1306.89 ; U5.G13@2878.1,1306.89 2878.1,1301.89 2877,1300.79 2877,1241.1 C27.1@2898.1,1220 ; U5.C13@2956.84,1306.89 2956.84,1278.16 2998.1,1236.9 C28.1@2998.1,1220 ; U5.C1@2956.84,1543.11 2956.84,1584.84 2993.1,1621.1 C12.1@2993.1,1650 ; U5.A8@2996.21,1405.31 3098.41,1405.31 C22.1@3105,1410 ; U5.A3@2996.21,1503.74 3010,1503.74 3024.26,1518 3070,1518 3073,1515 C17.1@3105,1515
  TOP w20: v2(2468,2038) 2468,2007 C6.1@2490,1985 2508,2003 v2(2508,2039) ; v1(2635,1394.25) 2635,1395 2663.1,1423.1 C21.1@2663.1,1425 ; v2(2644,1241) 2647.92,1244.92 2647.92,1257.92 C25.1@2665,1275 ; v2(2660,1543.81) 2660,1508.1 C18.1@2663.1,1505 ; v2(2805,1190) 2805,1191.05 2833.1,1219.15 C26.1@2833.1,1220 ; v2(2867,1187) 2867,1190 2897,1220 C27.1@2898.1,1220 ; C12.1@2993.1,1650 v2(3023.1,1680) ; C28.1@2998.1,1220 3033,1185.1 v2(3033,1184) ; C22.1@3105,1410 3105,1422 v2(3131,1448) ; C17.1@3105,1515 3105,1557.15 v2(3105.54,1557.69)
  L2_GND w8: v2(2644,1241) 2646,1241 2687.74,1282.74 2773.74,1282.74 2799.4,1308.4 v3(2799.4,1326.7) ; v3(2878.1,1523.43) 2878.1,1575.1 2889,1586 2889,1608 v5(2912,1631) ; v3(2897.79,1326.57) 2897.79,1299.21 2907.95,1289.05 2907.95,1269.2 v5(2911.15,1266) ; v3(2976.53,1444.69) 2998.69,1444.69 3010,1456 3119,1456 3127,1448 v2(3131,1448)
  L3_SIG w30: v2(1181,846) 1700,846 1805,951 1805,1072 1837,1104 2018,1104 2150,972 2287,972 2324,1009 2570,1009 v2(2573,1012)
  L4_VCC w20: 3110.08,2000 JP2.2@3148.1,2000 ; 3148.1,1961.98 JP2.2@3148.1,2000 ; 3148.1,2038.02 JP2.2@3148.1,2000 ; 3186.12,2000 JP2.2@3148.1,2000 ; 3230.08,940 JP4.3@3268.1,940 ; 3268.1,901.98 JP4.3@3268.1,940 ; 3268.1,978.02 JP4.3@3268.1,940 ; 3306.12,940 JP4.3@3268.1,940
  L5_GND w10: v7(2890,1230) 2890,1247.73 2904.17,1261.9 2907.05,1261.9 v5(2911.15,1266) ; v7(2905,1650) 2905,1638 v5(2912,1631) 2925,1644 v7(2925,1650)
  BOTTOM w20: SB24.1@1135,835 1170,835 v2(1181,846) ; v2(2805,1190) 2805,1195 2830,1220 C98.1@2833.1,1220 ; v2(2867,1187) 2867,1190 2897,1220 C97.1@2898.1,1220 ; v2(3015.17,1611.29) 3018,1614.12 3018,1618 3040,1640 R93.2@3040,1645 ; C89.1@3105,1410 3105,1422 v2(3131,1448)
  BOTTOM w30: v2(2573,1012) 2573,1133 2644,1204 v2(2644,1241)
VDD_STL: C34.1 C46.1 JP6.2 R45.2 R53.2 R54.2 U8.8 U11.1 U11.5 | length 1891.9
  TOP w10: U11.5@4703.57,525.94 4682.16,525.94 C46.1@4653.1,555 4678.1,580 4726,580 4762.63,616.63 U11.1@4762.63,644.06 ; U8.8@4792.63,928.94 4792.63,872.37 C34.1@4795,870
  TOP w20: R45.2@3965,1065 v1(3995,1095) ; v1(4615,555) C46.1@4653.1,555 ; v1(4683.1,818.1) R53.2@4683.1,775 R54.2@4738.1,775 ; C34.1@4795,870 v1(4835,870) 4893.1,870 JP6.2@4913.1,890
  L3_SIG w20: v1(4683.1,818.1) 4783.1,818.1 v1(4835,870)
  BOTTOM w20: v1(3995,1095) 4028,1095 4068,1055 4505,1055 4640,920 4640,861.2 v1(4683.1,818.1) 4615,750 v1(4615,555)
VDDA: C7.1 C8.1 L1.2 R18.2 U5.L2 | length 499.3
  TOP w15: R18.2@2675,1710 2784.17,1600.83 v1(2784.17,1585.96)
  TOP w20: L1.2@2565,1905 C7.1@2565,1835 2565,1785 C8.1@2600,1750 2635,1750 R18.2@2675,1710
  L2_GND w8: v1(2784.17,1585.96) 2784.17,1585.17 2784,1585 2784,1559 2796.25,1546.75 2796.25,1537.54 2799.36,1534.43 v3(2799.36,1523.43)
VIN: C45.1 CN15.8 U10.3 | length 511.2
  TOP w20: 2260.08,547.5 C45.1@2323.1,547.5 ; 2323.1,509.98 C45.1@2323.1,547.5 ; 2323.1,585.02 C45.1@2323.1,547.5 ; 2386.12,547.5 C45.1@2323.1,547.5 ; 2405.56,534.45 U10.3@2449.08,534.45 ; 2449.08,506.43 U10.3@2449.08,534.45 ; 2449.08,562.47 U10.3@2449.08,534.45 ; 2492.6,534.45 U10.3@2449.08,534.45
  BOTTOM w20: 2325.08,430 CN15.8@2353.1,430 ; 2353.1,374.48 CN15.8@2353.1,430 ; 2353.1,485.52 CN15.8@2353.1,430 ; 2381.12,430 CN15.8@2353.1,430
  other v1: 2275,470 2300,470 2275,495 2300,495
VL: C56.1 C57.1 C58.1 L6.2 L7.1 U15.1 | length 521.3
  TOP w20: 2151.17,239.59 U15.1@2151.17,255.61 2174.69,255.61 ; 2161.1,81.98 L7.1@2161.1,140 ; 2161.1,198.02 L7.1@2161.1,140 ; 2192.12,140 L7.1@2161.1,140 ; 2210.08,223 C56.1@2248.1,223 ; 2248.1,191.98 C56.1@2248.1,223 ; 2248.1,254.02 C56.1@2248.1,223 ; 2286.12,223 C56.1@2248.1,223 ; 2299.08,160 C57.1@2323.1,160 ; 2323.1,185.52 C57.1@2323.1,160 ; 2327.58,240 L6.2@2353.1,240 ; 2347.12,160 C57.1@2323.1,160 ; 2349.08,160 C58.1@2373.1,160 2373.1,185.52 ; 2353.1,215.98 L6.2@2353.1,240 ; 2353.1,264.02 L6.2@2353.1,240
VREF+: C3.1 C13.1 C14.1 R18.1 SB2.2 U5.L1 | length 1850
  TOP w10: 2757,1579 2763,1579 2775.04,1566.96 2778.04,1566.96 2799.36,1545.64 U5.L1@2799.36,1543.11
  TOP w15: R18.1@2675,1650 2675,1643 2736,1582 2754,1582 2757,1579
  TOP w20: C14.1@2565,1575 2580,1590 2580,1640 C13.1@2600,1660 2613,1673 v2(2642,1673) 2652,1673 R18.1@2675,1650 ; C3.1@3153.1,2165 SB2.2@3218.1,2165 3218.1,2107.6 3210.08,2099.58 v2(3210.08,2099.5)
  L3_SIG w20: v2(2410,2097) 2421,2086 3196.58,2086 v2(3210.08,2099.5)
  BOTTOM w20: v2(2410,2097) 2410,2007 2474,1943 2512,1943 2642,1813 v2(2642,1673)
pads on no net: "B2. " "CN4. " "CN6. " "CN12. " "CN17. " "SW1. " "U16. " "U17. " B2.7 B2.8 CN1.2 CN1.3 CN1.12 CN1.13 CN1.18 CN1.22 CN1.24 CN1.31 CN1.32 CN3.9 CN3.10 CN4.7 CN4.8 CN4.9 CN12.5 CN12.7 CN13.11 CN13.12 CN17.11 CN17.12 CN17.13 CN17.14 U4.E3 U4.G2 U4.H6 U6.4 U6.11 U6.14 U6.21 U6.22 U6.40 U6.41 U6.42 U6.43 U6.45 U6.46 U11.6 U15.5 U18.19 U18.20 U18.23 U18.24 U21.10 U21.12 U21.13 U21.14 U21.15 U21.18 U21.26 U21.27 U21.28 U21.30 U21.31 U21.32 U21.33 U21.38 U23.E1 U24.E1
copper on no net: | length 1500
  TOP w8: 1458,94 1518,94 ; 1458,94 1458,154 ; 1458,94 1518,94 ; 1458,94 1458,154 ; 1458,154 1468,154 ; 1458,154 1468,154 ; 1468,154 1518,154 ; 1468,154 1518,154 ; 1518,94 1518,154 ; 1518,94 1518,154 ; 1458,13 1518,13 1518,73 1458,73 1458,13
  BOTTOM w8: 1808,73 1818,73 ; 1808,73 1808,13 1868,13 1868,73 ; 1808,73 1818,73 ; 1808,94 1868,94 ; 1808,94 1808,154 ; 1808,94 1868,94 ; 1808,94 1808,154 ; 1808,154 1818,154 ; 1808,154 1818,154 ; 1818,73 1868,73 ; 1818,73 1868,73 ; 1818,154 1868,154 ; 1818,154 1868,154 ; 1868,94 1868,154 ; 1868,94 1868,154

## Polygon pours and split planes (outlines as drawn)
3V3_OUT on L4_VCC "L4_VCC-3V3_OUT" (solid, pour order 215): 1327 vertices, not listed, extent 2535,320 4830,2200
VDD on L4_VCC "L4_VCC-VDD" (solid, pour order 218): 944 vertices, not listed, extent 20.04,20.04 3129.98,2617.75
VDD on L4_VCC "L4_VCC-VDD 1" (solid, pour order 213): 462 vertices, not listed, extent 3700,380 4590,2065
VDD1 on L4_VCC "L4_VCC-VDD1" (solid, pour order 216): 603 vertices, not listed, extent 615,855 3590,2617.75
3V3_LCD on L4_VCC "L4_VCC-3V3_LCD" (solid, pour order 211): 357 vertices, not listed, extent 1020,1225 2410,1890
+3V3_ST_LINK on L4_VCC "L4_VCC-+3V3_ST_LINK" (solid, pour order 212): 539 vertices, not listed, extent 3910,435 4865,1655
+5V on L4_VCC "L4_VCC-+5V" (solid, pour order 217): 2636 vertices, not listed, extent 1500.02,14.13 5102.06,2617.75
VDD_MCU on L4_VCC "L4_VCC-VDD_MCU" (solid, pour order 214): 125 vertices, not listed, extent 2430.02,880 3380,2054.98
no net on LAY3 (solid, pour order 257): 23 vertices, not listed, extent 5018.1,-400 5118.1,-300
no net on LAY3 (solid, pour order 258): 23 vertices, not listed, extent 5118.1,-300 5218.1,-200
no net on LAY3 (solid, pour order 268): 203.1,560 203.1,600 3.1,600 3.1,1220 3.1,1455 3.1,1970 1683.1,1970 1683.1,1010 2033.1,1010 2033.1,655 1683.1,655 1683.1,600 1443.1,600 1443.1,560 203.1,560
no net on LAY3 (solid, pour order 267): 3.1,1047 3.1,1520 449.1,1520 449.1,1776.46 665.1,1776.46 665.1,1520 577.1,1520 577.1,1047 3.1,1047
no net on LAY3 (solid, pour order 262): 4538.1,105 ccw(c4478.1,105) 4478.1,165 ccw(c4478.1,105) 4418.1,105 ccw(c4478.1,105) 4478.1,45 ccw(c4478.1,105) 4538.1,105
no net on LAY3 (solid, pour order 264): 4722.1,2486 ccw(c4662.1,2486) 4662.1,2546 ccw(c4662.1,2486) 4602.1,2486 ccw(c4662.1,2486) 4662.1,2426 ccw(c4662.1,2486) 4722.1,2486
no net on LAY3 (solid, pour order 266): 388.1,2300 ccw(c328.1,2300) 328.1,2360 ccw(c328.1,2300) 268.1,2300 ccw(c328.1,2300) 328.1,2240 ccw(c328.1,2300) 388.1,2300
no net on LAY3 (solid, pour order 261): 4722.1,2486 ccw(c4662.1,2486) 4662.1,2546 ccw(c4662.1,2486) 4602.1,2486 ccw(c4662.1,2486) 4662.1,2426 ccw(c4662.1,2486) 4722.1,2486
no net on LAY3 (solid, pour order 263): 323.1,460 ccw(c263.1,460) 263.1,520 ccw(c263.1,460) 203.1,460 ccw(c263.1,460) 263.1,400 ccw(c263.1,460) 323.1,460
no net on LAY3 (solid, pour order 265): 323.1,460 ccw(c263.1,460) 263.1,520 ccw(c263.1,460) 203.1,460 ccw(c263.1,460) 263.1,400 ccw(c263.1,460) 323.1,460
no net on LAY3 (solid, pour order 260): 23 vertices, not listed, extent 5018.1,-400 5118.1,-300
no net on LAY3 (solid, pour order 259): 23 vertices, not listed, extent 5118.1,-300 5218.1,-200
no net on Drill Drawing (solid): 13399,5371 13599,5371 13549,5121 13449,5121 13399,5371
no net on Drill Drawing (solid): 13272,4324.43 13372,4324.43 13372,5079.57 13272,5079.57 13272,4324.43
no net on Drill Drawing (solid): 13041,5370 13241,5370 13171,4810 13121,4810 13041,5370
no net on Drill Drawing (solid): 13593,4026 13393,4026 13443,4276 13543,4276 13593,4026
3V3_OUT on TOP "TOP-3V3_OUT" (solid, pour order 187): 45 vertices, not listed, extent 1455,2505 1660,2605
3V3_OUT on TOP "TOP-3V3_OUT 1" (solid, pour order 168): 33 vertices, not listed, extent 3650,2105 3698.08,2205
3V3_OUT on TOP "TOP-3V3_OUT 2" (solid, pour order 198): 31 vertices, not listed, extent 3365,580 3785,990
1V8_OUT on TOP "TOP-1V8_OUT" (solid, pour order 167): 682,705 688,711 747,711 755,703 755,663 741,649 688,649 682,655 682,705
1V8_OUT on TOP "TOP-1V8_OUT 1" (solid, pour order 172): 3070,680 3080,690 3170,690 3175,685 3175,630 3170,625 3080,625 3070,635 3070,680
1V8_OUT on TOP "TOP-1V8_OUT 2" (solid, pour order 171): 799,2009 799,1947 794,1942 730,1942 724,1948 724,2015 729,2020 788,2020 799,2009
1V8_OUT on TOP "TOP-1V8_OUT 3" (solid, pour order 196): 72 vertices, not listed, extent 3673,579 4011,1026
1V8_SW on TOP "TOP-1V8_SW" (solid, pour order 170): 39 vertices, not listed, extent 3670,520 3824,590
3V3_SW on TOP "TOP-3V3_SW" (solid, pour order 169): 3380,530 3370,540 3370,585 3380,595 3383.98,595 3383.98,543.48 3496.02,543.48 3496.02,595 3517,595 3546.5,565.5 3546.5,561.5 3515,530 3380,530
VDD on TOP "TOP-VDD" (solid, pour order 191): 3417,1832 3385,1864 3385,2057 3388,2060 3431,2060 3434,2057 3434,1912 3446,1900 3741,1900 3746.5,1894.5 3746.5,1836.5 3742,1832 3417,1832
BLGND on TOP "TOP-BLGND" (solid, pour order 185): 41 vertices, not listed, extent 2035.02,395 2130,580
LEDA on TOP "TOP-LEDA" (solid, pour order 192): 19 vertices, not listed, extent 1850,300 2015,585
VL on TOP "TOP-VL" (solid, pour order 190): 98 vertices, not listed, extent 2133.1,55 2403.1,280
USB_OTGFS_VBUS on TOP "TOP-USB_OTGFS_VBUS" (solid, pour order 178): 37 vertices, not listed, extent 2925,206.65 3040,380
5V_USB_CHARGER on TOP "TOP-5V_USB_CHARGER" (solid, pour order 188): 30 vertices, not listed, extent 3500,1345 3685,1530
VIN on TOP "TOP-VIN" (solid, pour order 193): 36 vertices, not listed, extent 2245,455 2520,605
+3V3_ST_LINK on TOP "TOP-+3V3_ST_LINK" (solid, pour order 175): 22 vertices, not listed, extent 4390,985 4615,1050
GND on TOP "TOP-GND" (solid, pour order 194): 457 vertices, not listed, extent 4904,1084 5101,1439
GND on TOP "TOP-GND 1" (solid, pour order 195): 389 vertices, not listed, extent 2667,18 3085,213
GND on TOP "TOP-GND 2" (solid, pour order 174): 20 vertices, not listed, extent 4450,1070 4620,1140
GND on TOP "TOP-GND 3" (solid, pour order 180): 426,2391 431,2396 550,2396 559,2387 559,2324 550,2315 435,2315 426,2324 426,2391
GND on TOP "TOP-GND 4" (solid, pour order 197): 51 vertices, not listed, extent 2250,635 2550,880
GND on TOP "TOP-GND 5" (solid, pour order 186): 27 vertices, not listed, extent 2780,1755 2980,1900
GND on TOP "TOP-GND 6" (solid, pour order 181): 1252.69,2391 1257.69,2396 1376.69,2396 1385.69,2387 1385.69,2323 1375.69,2313 1260.69,2313 1252.69,2321 1252.69,2391
GND on TOP "TOP-GND 7" (solid, pour order 177): 3595,670 3587.5,677.5 3587.5,737.98 3612.02,737.98 3612.02,772.02 3587.5,772.02 3587.5,812.5 3595,820 3639,820 3653,806 3653,678 3645,670 3595,670
GND on TOP "TOP-GND 8" (solid, pour order 176): 3869.02,792.71 3878.29,801.98 3932.02,801.98 3940,794 3940,672 3932,664 3881,664 3869.02,675.98 3869.02,727.98 3895.12,727.98 3895.12,762.02 3869.02,762.02 3869.02,792.71
GND on TOP "TOP-GND 9" (solid, pour order 189): 70 vertices, not listed, extent 3729,1264 3886,1497
GND on TOP "TOP-GND 10" (solid, pour order 184): 17 vertices, not listed, extent 3876,383 3960,570
GND on TOP "TOP-GND 11" (solid, pour order 182): 22 vertices, not listed, extent 3600.5,399 3701,550
+5V on TOP "TOP-+5V" (solid, pour order 179): 3768,394 3760,402 3760,452 3834.5,526.5 3834.5,544.5 3850,560 3855,560 3855,477.02 3827.98,477.02 3827.98,442.98 3855,442.98 3855,408 3841,394 3768,394
+5V on TOP "TOP-+5V 1" (solid, pour order 183): 29 vertices, not listed, extent 3485,400 3605,570
E5V on TOP "TOP-E5V" (solid, pour order 166): 3036,591 3041,596 3074,596 3080,590 3080,523 3074,517 3041,517 3036,522 3036,591
E5V on TOP "TOP-E5V 1" (solid, remove dead copper, pour order 199): 2738,535 2585,535 2515,605 2515,640 2585,710 2585,778.98 2649.12,778.98 2649.12,851.02 2585,851.02 2585,875 2600,890 2750,890 2761,879 2761,558 2738,535
U5V_ST_LINK on TOP "TOP-U5V_ST_LINK" (solid, pour order 173): 3465,1060 3455,1070 3455,1153.78 3482.02,1153.78 3482.02,1230 3497.98,1230 3497.98,1153.78 3535,1153.78 3535,1140.12 3496.48,1140.12 3496.48,1096.08 3535,1096.08 3535,1065 3530,1060 3465,1060
3V3_OUT on BOTTOM "BOTTOM-3V3_OUT" (solid, pour order 224): 330,665 325,670 325,686.69 330.02,691.71 330.02,710.24 354.02,710.24 354.02,775.28 330.02,775.28 330.02,790 365,790 370,785 370,670 365,665 330,665
3V3_OUT on BOTTOM "BOTTOM-3V3_OUT 1" (solid, pour order 227): 1995,40 1990,45 1990,110 1995,115 2055,115 2065,105 2065,45 2060,40 1995,40
3V3_OUT on BOTTOM "BOTTOM-3V3_OUT 2" (solid, pour order 223): 2540,360 2550,370 2610,370 2615,365 2615,325 2610,320 2560,320 2540,340 2540,360
3V3_OUT on BOTTOM "BOTTOM-3V3_OUT 3" (solid, pour order 230): 65 vertices, not listed, extent 3525,568 3640,686
1V8_OUT on BOTTOM "BOTTOM-1V8_OUT" (solid, pour order 232): 68 vertices, not listed, extent 3807,574 3925,702
VDD on BOTTOM "BOTTOM-VDD" (solid, pour order 225): 2634,1063 2641,1070 2707,1070 2712,1065 2712,1016 2710,1014 2640,1014 2634,1020 2634,1063
VDD on BOTTOM "BOTTOM-VDD 1" (solid, pour order 248): 93 vertices, not listed, extent 3050,865 3895,1190
AMP_5V on BOTTOM "BOTTOM-AMP_5V" (solid, pour order 239): 18 vertices, not listed, extent 1330,695 1425,939
AMP_VDD on BOTTOM "BOTTOM-AMP_VDD" (solid, pour order 229): 18 vertices, not listed, extent 1350,1035 1425,1245
CAL_D on BOTTOM "BOTTOM-CAL_D" (solid, pour order 243): 18 vertices, not listed, extent 1595,1380 1675,1695
SH0_D on BOTTOM "BOTTOM-SH0_D" (solid, pour order 242): 18 vertices, not listed, extent 1595,1720 1675,2000
SH1_D on BOTTOM "BOTTOM-SH1_D" (solid, pour order 240): 18 vertices, not listed, extent 1595,1035 1675,1315
SH2_D on BOTTOM "BOTTOM-SH2_D" (solid, pour order 241): 18 vertices, not listed, extent 1595,690 1675,970
T50_6 on BOTTOM "BOTTOM-T50_6" (solid, pour order 247): 47 vertices, not listed, extent 1328,880 1575,1915
3V3_LCD on BOTTOM "BOTTOM-3V3_LCD" (solid, pour order 234): 18 vertices, not listed, extent 220,685 310,895
VDD_LCD on BOTTOM "BOTTOM-VDD_LCD" (solid, pour order 236): 18 vertices, not listed, extent 465,685 555,895
5V_USB_CHARGER on BOTTOM "BOTTOM-5V_USB_CHARGER" (solid, pour order 221): 4828,1156 4831,1159 4890,1159 4897,1152 4897,1120 4895,1118 4831,1118 4828,1121 4828,1156
5V_USB_CHARGER on BOTTOM "BOTTOM-5V_USB_CHARGER 1" (solid, pour order 231): 3709,1333 3699,1323 3654,1323 3646,1331 3646,1442 3653,1449 3702,1449 3709,1442 3709,1333
VIN on BOTTOM "BOTTOM-VIN" (solid, pour order 245): 2260,525 2270,535 2380,535 2395,520 2395,385 2375,365 2275,365 2260,380 2260,525
GND on BOTTOM "BOTTOM-GND" (solid, pour order 235): 26 vertices, not listed, extent 1255.69,2313 1384.69,2394
GND on BOTTOM "BOTTOM-GND 1" (solid, pour order 233): 26 vertices, not listed, extent 429,2315 558,2394
GND on BOTTOM "BOTTOM-GND 2" (solid, pour order 238): 3617,412 3603,426 3603,433.77 3604.02,434.78 3604.02,544.01 3607.99,547.98 3613.29,547.98 3624.81,559.5 3638.5,559.5 3696,502 3696,414 3694,412 3617,412
GND on BOTTOM "BOTTOM-GND 3" (solid, pour order 237): 3958,402 3952,396 3896,396 3887.02,404.98 3887.02,550.46 3898.75,550.46 3918.28,570 3930,570 3958,542 3958,402
+5V on BOTTOM "BOTTOM-+5V" (solid, pour order 226): 635,530 635,595 640,600 695,600 700,595 700,530 695,525 640,525 635,530
+5V on BOTTOM "BOTTOM-+5V 1" (solid, pour order 246): 256 vertices, not listed, extent 3748,394 3867,630
+5V on BOTTOM "BOTTOM-+5V 2" (solid, pour order 244): 84 vertices, not listed, extent 3460,431 3589,615
E5V on BOTTOM "BOTTOM-E5V" (solid, pour order 222): 3043,510 3038,515 3038,586 3046,594 3072,594 3078,588 3078,515 3073,510 3043,510
E5V on BOTTOM "BOTTOM-E5V 1" (solid, pour order 228): 2759,846 2752,839 2685,839 2676,848 2676,899 2699,922 2750,922 2759,913 2759,846
1V8_OUT on L3_SIG "L3_SIG-1V8_OUT" (solid, pour order 204): 682,705 688,711 747,711 755,703 755,663 741,649 688,649 682,655 682,705
1V8_OUT on L3_SIG "L3_SIG-1V8_OUT 1" (solid, pour order 207): 1981,634 1976,639 1976,673 2004.98,701.98 2085.02,701.98 2093,694 2093,643 2084,634 1981,634
1V8_OUT on L3_SIG "L3_SIG-1V8_OUT 2" (solid, pour order 206): 3070,680 3080,690 3170,690 3175,685 3175,630 3170,625 3080,625 3070,635 3070,680
VDD on L3_SIG "L3_SIG-VDD" (solid, pour order 209): 35 vertices, not listed, extent 3432,1530 3766,1576
VDD on L3_SIG "L3_SIG-VDD 1" (solid, pour order 210): 3218,1768 3388,1938 3388,1942.67 3388.02,1942.68 3388.02,2054.02 3394,2060 3432,2060 3438,2054 3438,1920 3232,1714 3137,1714 3128.02,1722.98 3128.02,1752.02 3144,1768 3218,1768
USB_OTGFS_VBUS on L3_SIG "L3_SIG-USB_OTGFS_VBUS" (solid, pour order 208): 3065,380 3170,275 3170,240 3155,225 3130,225 3030,325 3010,325 2995,340 2995,375 3000,380 3065,380
+5V on L3_SIG "L3_SIG-+5V" (solid, pour order 203): 680,525 675.02,529.98 675.02,585.02 685,595 730,595 735,590 735,530 730,525 680,525
+5V on L3_SIG "L3_SIG-+5V 1" (solid, pour order 202): 1525,515 1530,520 1575,520 1580,515 1580,465 1575,460 1530,460 1525,465 1525,515
U5V_ST_LINK on L3_SIG "L3_SIG-U5V_ST_LINK" (solid, pour order 205): 3465,1085 3470,1090 3530,1090 3535,1085 3535,1030 3530,1025 3470,1025 3465,1030 3465,1085
no net on Top Solder (solid, pour order 249): 1378,83 1378,3 1948,3 1948,83 1378,83
no net on Top Solder (solid, pour order 250): 1378,164 1378,84 1948,84 1948,164 1378,164
AGND on L5_GND "L5_GND-AGND" (solid, pour order 219): 28 vertices, not listed, extent 20.04,1726 1169,2345
GND on L5_GND "L5_GND-GND" (solid, pour order 220): 686 vertices, not listed, extent 20.04,10.04 5098.06,2617.75
BLGND on L2_GND "L2_GND-BLGND" (solid, pour order 200): 24 vertices, not listed, extent 1835,20.04 2525,579
GND on L2_GND "L2_GND-GND" (solid, remove dead copper, pour order 201): 527 vertices, not listed, extent 20.04,10.04 5098.06,2617.75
